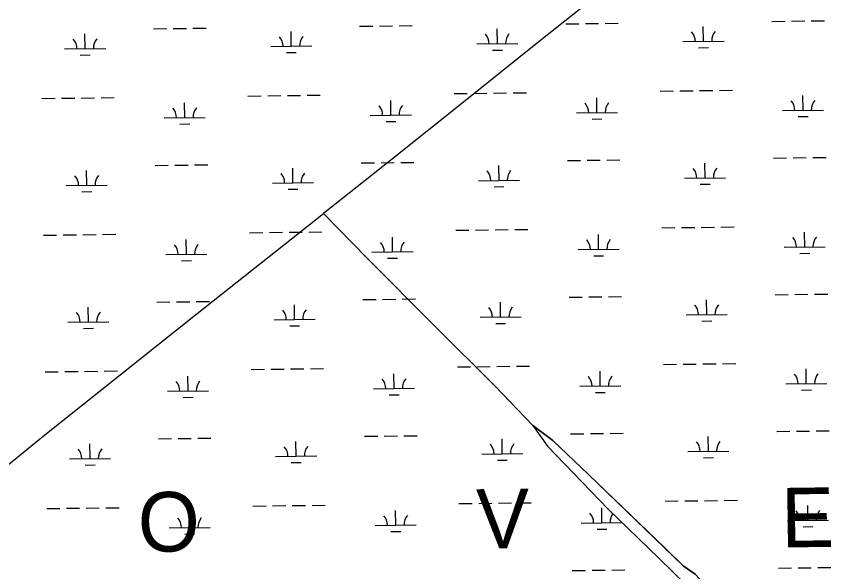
# Model space of a CAD drawing. Extents: x 3694830 to 3732949, y 415201 to 440970.
# Drawn here: x 3721259 to 3723273, y 422881 to 424231 of the extents above; entities that cross this region are included whole.
import ezdxf

# ---------------------------------------------------------------- set-up
doc = ezdxf.new("R2010")
doc.units = 0
for name, color, linetype in [('V-TOPO-GNAM-IDEN', 7, 'Continuous'), ('V-TOPO-SHOR', 7, 'Continuous'), ('V-WETL-SWMP', 7, 'Continuous')]:
    doc.layers.add(name, color=color, linetype=linetype)

msp = doc.modelspace()

# ---------------------------------------------------------------- linework, layer by layer
at = {"layer": 'V-TOPO-SHOR'}
for points in [[(3724038.3, 425348.9), (3723786.8, 425156.9), (3723547.1, 424963.7), (3723407.5, 424856.6), (3723207.5, 424699.3), (3722960.3, 424507.6), (3722773.6, 424363), (3722535.6, 424174.1), (3722351.3, 424025.9), (3722170.6, 423881.7), (3722006.1, 423752.1)], [(3721128.3, 423051.5), (3721324.1, 423210), (3721699, 423509.1), (3722006.1, 423752.1)], [(3722006.1, 423752.1), (3722111.6, 423644.1), (3722278.4, 423476.8), (3722424.2, 423332.1), (3722515.9, 423236.4), (3722551.8, 423185.8)], [(3722515.9, 423236.4), (3722564.9, 423200), (3722651.8, 423117), (3722837.2, 422938.2), (3722882.2, 422894.7), (3722911.1, 422874.5), (3722923, 422862.3), (3722926.1, 422850), (3722935.2, 422831.4), (3722965.6, 422798.2), (3723006.3, 422758.3), (3723028.1, 422743.6), (3723045.1, 422728.6), (3723084.6, 422693), (3723130.8, 422664.9), (3723153, 422652.3), (3723164, 422655), (3723176.5, 422664.2), (3723180.6, 422667.3), (3723193.3, 422674.8), (3723211.5, 422683.1), (3723238, 422684.7), (3723233.6, 422648)], [(3722551.8, 423185.8), (3722699.6, 423032.7), (3722822.2, 422913.7), (3722892.9, 422845.3)]]:
    msp.add_lwpolyline(points, dxfattribs=at)
at = {"layer": 'V-WETL-SWMP'}
for p, q in [((3722142.4, 424208.3), (3722174.4, 424208.7)), ((3722190.4, 424208.9), (3722222.4, 424209.3)), ((3722596.3, 424213.7), (3722628.3, 424214.1)), ((3722644.3, 424214.3), (3722676.3, 424214.7)), ((3722692.3, 424214.9), (3722724.3, 424215.2)), ((3723098.2, 424219.7), (3723130.2, 424220.1)), ((3723146.2, 424220.3), (3723178.2, 424220.7)), ((3723194.2, 424220.8), (3723226.2, 424221.2)), ((3721426.1, 424153.3), (3721425.6, 424189.3)), ((3721592.5, 424201.7), (3721624.5, 424202.1)), ((3721640.5, 424202.3), (3721672.5, 424202.7)), ((3721688.5, 424202.9), (3721720.5, 424203.3)), ((3721927.9, 424159.3), (3721927.5, 424195.3)), ((3722094.4, 424207.7), (3722126.4, 424208.1)), ((3722429.8, 424165.3), (3722429.4, 424201.3)), ((3722931.7, 424171.3), (3722931.2, 424207.3)), ((3722881.7, 424170.7), (3722981.7, 424171.9)), ((3721376.1, 424152.7), (3721476, 424153.9)), ((3721877.9, 424158.7), (3721977.9, 424159.9)), ((3722379.8, 424164.7), (3722479.8, 424165.9)), ((3722418, 424149.7), (3722442, 424150)), ((3722919.9, 424155.7), (3722943.9, 424156)), ((3721414.2, 424137.8), (3721438.2, 424138)), ((3721916.1, 424143.7), (3721940.1, 424144)), ((3722826.3, 424049.9), (3722858.3, 424050.3)), ((3722874.3, 424050.5), (3722906.3, 424050.9)), ((3722922.3, 424051.1), (3722954.3, 424051.5)), ((3722970.3, 424051.7), (3723002.3, 424052)), ((3721320.6, 424032), (3721352.6, 424032.4)), ((3721368.6, 424032.6), (3721400.6, 424032.9)), ((3721416.6, 424033.1), (3721448.6, 424033.5)), ((3721464.6, 424033.7), (3721496.6, 424034.1)), ((3721822.5, 424038), (3721854.5, 424038.4)), ((3721870.5, 424038.5), (3721902.5, 424038.9)), ((3721918.5, 424039.1), (3721950.5, 424039.5)), ((3721966.5, 424039.7), (3721998.5, 424040.1)), ((3722170.4, 423991.4), (3722170, 424027.4)), ((3722324.4, 424044), (3722356.4, 424044.3)), ((3722372.4, 424044.5), (3722404.4, 424044.9)), ((3722420.4, 424045.1), (3722452.4, 424045.5)), ((3722468.4, 424045.7), (3722500.4, 424046.1)), ((3722672.3, 423997.4), (3722671.9, 424033.4)), ((3723174.2, 424003.3), (3723173.7, 424039.3)), ((3721668.5, 423985.4), (3721668.1, 424021.4)), ((3722120.4, 423990.8), (3722220.4, 423992)), ((3722622.3, 423996.8), (3722722.3, 423998)), ((3723124.2, 424002.8), (3723224.2, 424003.9)), ((3723162.3, 423987.8), (3723186.3, 423988.1)), ((3721618.5, 423984.8), (3721718.5, 423986)), ((3721656.7, 423969.8), (3721680.7, 423970.1)), ((3722158.6, 423975.8), (3722182.6, 423976.1)), ((3722660.5, 423981.8), (3722684.5, 423982.1)), ((3723102.1, 423887), (3723134.1, 423887.4)), ((3723150.1, 423887.6), (3723182.1, 423888)), ((3723198.1, 423888.2), (3723230.1, 423888.6)), ((3721596.5, 423869.1), (3721628.5, 423869.5)), ((3721644.5, 423869.7), (3721676.5, 423870)), ((3721692.5, 423870.2), (3721724.5, 423870.6)), ((3722098.4, 423875.1), (3722130.4, 423875.5)), ((3722146.4, 423875.6), (3722178.4, 423876)), ((3722194.4, 423876.2), (3722226.4, 423876.6)), ((3722433.8, 423832.6), (3722433.3, 423868.6)), ((3722600.3, 423881.1), (3722632.3, 423881.4)), ((3722648.3, 423881.6), (3722680.3, 423882)), ((3722696.3, 423882.2), (3722728.3, 423882.6)), ((3722935.6, 423838.6), (3722935.2, 423874.6)), ((3721430, 423820.7), (3721429.6, 423856.7)), ((3721931.9, 423826.7), (3721931.5, 423862.7)), ((3721881.9, 423826.1), (3721981.9, 423827.3)), ((3722383.8, 423832), (3722483.8, 423833.2)), ((3722885.6, 423838), (3722985.6, 423839.2)), ((3721380, 423820.1), (3721480, 423821.3)), ((3721920.1, 423811.1), (3721944.1, 423811.4)), ((3722421.9, 423817.1), (3722445.9, 423817.4)), ((3722923.8, 423823.1), (3722947.8, 423823.3)), ((3721418.2, 423805.1), (3721442.2, 423805.4)), ((3721826.5, 423705.3), (3721858.5, 423705.7)), ((3721874.5, 423705.9), (3721906.5, 423706.3)), ((3721922.5, 423706.5), (3721954.5, 423706.8)), ((3721970.5, 423707), (3722002.5, 423707.4)), ((3722328.4, 423711.3), (3722360.4, 423711.7)), ((3722376.4, 423711.9), (3722408.4, 423712.3)), ((3722424.4, 423712.5), (3722456.3, 423712.8)), ((3722472.3, 423713), (3722504.3, 423713.4)), ((3722830.2, 423717.3), (3722862.2, 423717.7)), ((3722878.2, 423717.9), (3722910.2, 423718.2)), ((3722926.2, 423718.4), (3722958.2, 423718.8)), ((3722974.2, 423719), (3723006.2, 423719.4)), ((3723178.1, 423670.7), (3723177.7, 423706.7)), ((3721324.6, 423699.3), (3721356.6, 423699.7)), ((3721372.6, 423699.9), (3721404.6, 423700.3)), ((3721420.6, 423700.5), (3721452.6, 423700.9)), ((3721468.6, 423701.1), (3721500.6, 423701.4)), ((3721672.5, 423652.7), (3721672.1, 423688.7)), ((3722174.4, 423658.7), (3722174, 423694.7)), ((3722676.3, 423664.7), (3722675.8, 423700.7)), ((3722626.3, 423664.1), (3722726.3, 423665.3)), ((3723128.1, 423670.1), (3723228.1, 423671.3)), ((3721622.5, 423652.1), (3721722.5, 423653.3)), ((3722124.4, 423658.1), (3722224.4, 423659.3)), ((3722664.4, 423649.1), (3722688.4, 423649.4)), ((3723166.3, 423655.1), (3723190.3, 423655.4)), ((3721660.7, 423637.2), (3721684.7, 423637.5)), ((3722162.6, 423643.2), (3722186.6, 423643.4)), ((3722198.3, 423543.6), (3722230.3, 423544)), ((3722604.2, 423548.4), (3722636.2, 423548.8)), ((3722652.2, 423549), (3722684.2, 423549.4)), ((3722700.2, 423549.6), (3722732.2, 423549.9)), ((3723106.1, 423554.4), (3723138.1, 423554.8)), ((3723154.1, 423555), (3723186.1, 423555.4)), ((3723202.1, 423555.5), (3723234.1, 423555.9)), ((3721434, 423488), (3721433.6, 423524)), ((3721600.5, 423536.4), (3721632.5, 423536.8)), ((3721648.5, 423537), (3721680.5, 423537.4)), ((3721696.5, 423537.6), (3721728.5, 423538)), ((3721935.9, 423494), (3721935.4, 423530)), ((3722102.4, 423542.4), (3722134.4, 423542.8)), ((3722150.4, 423543), (3722182.4, 423543.4)), ((3722437.7, 423500), (3722437.3, 423536)), ((3722939.6, 423506), (3722939.2, 423542)), ((3722889.6, 423505.4), (3722989.6, 423506.6)), ((3721384, 423487.4), (3721484, 423488.6)), ((3721885.9, 423493.4), (3721985.9, 423494.6)), ((3722387.7, 423499.4), (3722487.7, 423500.6)), ((3722425.9, 423484.4), (3722449.9, 423484.7)), ((3722927.8, 423490.4), (3722951.8, 423490.7)), ((3721422.2, 423472.4), (3721446.2, 423472.7)), ((3721924, 423478.4), (3721948, 423478.7)), ((3722834.2, 423384.6), (3722866.2, 423385)), ((3722882.2, 423385.2), (3722914.2, 423385.6)), ((3722930.2, 423385.8), (3722962.2, 423386.2)), ((3722978.2, 423386.4), (3723010.2, 423386.7)), ((3721328.6, 423366.7), (3721360.6, 423367.1)), ((3721376.6, 423367.3), (3721408.6, 423367.6)), ((3721424.6, 423367.8), (3721456.6, 423368.2)), ((3721472.6, 423368.4), (3721504.6, 423368.8)), ((3721830.5, 423372.7), (3721862.5, 423373.1)), ((3721878.5, 423373.2), (3721910.4, 423373.6)), ((3721926.4, 423373.8), (3721958.4, 423374.2)), ((3721974.4, 423374.4), (3722006.4, 423374.8)), ((3722332.3, 423378.7), (3722364.3, 423379)), ((3722380.3, 423379.2), (3722412.3, 423379.6)), ((3722428.3, 423379.8), (3722460.3, 423380.2)), ((3722476.3, 423380.4), (3722508.3, 423380.8)), ((3722680.2, 423332.1), (3722679.8, 423368.1)), ((3723182.1, 423338), (3723181.7, 423374)), ((3721676.5, 423320.1), (3721676, 423356.1)), ((3722178.3, 423326.1), (3722177.9, 423362.1)), ((3722128.4, 423325.5), (3722228.3, 423326.7)), ((3722630.2, 423331.5), (3722730.2, 423332.7)), ((3723132.1, 423337.4), (3723232.1, 423338.6)), ((3723170.3, 423322.5), (3723194.3, 423322.8)), ((3721626.5, 423319.5), (3721726.5, 423320.7)), ((3721664.7, 423304.5), (3721688.7, 423304.8)), ((3722166.5, 423310.5), (3722190.5, 423310.8)), ((3722668.4, 423316.5), (3722692.4, 423316.8)), ((3722564.9, 423200), (3722515.9, 423236.4)), ((3722515.9, 423236.4), (3722551.8, 423185.8)), ((3723110.1, 423221.7), (3723142.1, 423222.1)), ((3723158.1, 423222.3), (3723190.1, 423222.7)), ((3723206.1, 423222.9), (3723238.1, 423223.3)), ((3721604.5, 423203.8), (3721636.4, 423204.2)), ((3721652.4, 423204.4), (3721684.4, 423204.7)), ((3721700.4, 423204.9), (3721732.4, 423205.3)), ((3722106.3, 423209.8), (3722138.3, 423210.2)), ((3722154.3, 423210.3), (3722186.3, 423210.7)), ((3722202.3, 423210.9), (3722234.3, 423211.3)), ((3722441.7, 423167.3), (3722441.3, 423203.3)), ((3722608.2, 423215.8), (3722640.2, 423216.1)), ((3722656.2, 423216.3), (3722688.2, 423216.7)), ((3722704.2, 423216.9), (3722736.2, 423217.3)), ((3722943.6, 423173.3), (3722943.1, 423209.3)), ((3721438, 423155.4), (3721437.5, 423191.4)), ((3721939.8, 423161.4), (3721939.4, 423197.4)), ((3722551.8, 423185.8), (3722699.6, 423032.7)), ((3722651.8, 423117), (3722564.9, 423200)), ((3721889.8, 423160.8), (3721989.8, 423162)), ((3722391.7, 423166.7), (3722491.7, 423167.9)), ((3722893.6, 423172.7), (3722993.6, 423173.9)), ((3721388, 423154.8), (3721487.9, 423156)), ((3721928, 423145.8), (3721952, 423146.1)), ((3722429.9, 423151.8), (3722453.9, 423152.1)), ((3722931.8, 423157.8), (3722955.8, 423158)), ((3721426.1, 423139.8), (3721450.1, 423140.1)), ((3722882.2, 422894.7), (3722651.8, 423117)), ((3721882.4, 423040.6), (3721914.4, 423041)), ((3721930.4, 423041.2), (3721962.4, 423041.5)), ((3721978.4, 423041.7), (3722010.4, 423042.1)), ((3722336.3, 423046), (3722368.3, 423046.4)), ((3722384.3, 423046.6), (3722416.3, 423047)), ((3722432.3, 423047.1), (3722464.3, 423047.5)), ((3722480.3, 423047.7), (3722512.3, 423048.1)), ((3722838.2, 423052), (3722870.2, 423052.4)), ((3722886.2, 423052.6), (3722918.2, 423052.9)), ((3722934.2, 423053.1), (3722966.2, 423053.5)), ((3722982.2, 423053.7), (3723014.2, 423054.1)), ((3723186.1, 423005.4), (3723185.6, 423041.4)), ((3721332.5, 423034), (3721364.5, 423034.4)), ((3721380.5, 423034.6), (3721412.5, 423035)), ((3721428.5, 423035.2), (3721460.5, 423035.6)), ((3721476.5, 423035.7), (3721508.5, 423036.1)), ((3721680.4, 422987.4), (3721680, 423023.4)), ((3721834.4, 423040), (3721866.4, 423040.4)), ((3722182.3, 422993.4), (3722181.9, 423029.4)), ((3722684.2, 422999.4), (3722683.8, 423035.4)), ((3722699.6, 423032.7), (3722822.2, 422913.7)), ((3723136.1, 423004.8), (3723236.1, 423006)), ((3721630.4, 422986.8), (3721730.4, 422988)), ((3722132.3, 422992.8), (3722232.3, 422994)), ((3722634.2, 422998.8), (3722733.3, 423000)), ((3722672.4, 422983.8), (3722696.4, 422984.1)), ((3723174.2, 422989.8), (3723198.2, 422990.1)), ((3721668.6, 422971.9), (3721692.6, 422972.1)), ((3722170.5, 422977.8), (3722194.5, 422978.1)), ((3722822.2, 422913.7), (3722892.9, 422845.3)), ((3722612.2, 422883.1), (3722644.2, 422883.5)), ((3722660.2, 422883.7), (3722692.2, 422884.1)), ((3722708.2, 422884.3), (3722740.2, 422884.6)), ((3722911.1, 422874.5), (3722882.2, 422894.7)), ((3723114, 422889.1), (3723146, 422889.5)), ((3723162, 422889.7), (3723194, 422890)), ((3723210, 422890.2), (3723242, 422890.6))]:
    msp.add_line(p, q, dxfattribs=at)
for centre, start, end in [((3722374.6, 424165.1), 359.9115, 41.4552), ((3722485, 424166.4), 139.9115, 181.4552), ((3722876.4, 424171.1), 359.9115, 41.4552), ((3722986.9, 424172.4), 139.9115, 181.4552), ((3721370.8, 424153.1), 359.9115, 41.4552), ((3721481.3, 424154.5), 139.9115, 181.4552), ((3721872.7, 424159.1), 359.9115, 41.4552), ((3721983.2, 424160.4), 139.9115, 181.4552), ((3721613.3, 423985.2), 359.9115, 41.4552), ((3721723.8, 423986.5), 139.9115, 181.4552), ((3722115.2, 423991.2), 359.9115, 41.4552), ((3722225.6, 423992.5), 139.9115, 181.4552), ((3722617, 423997.2), 359.9115, 41.4552), ((3722727.5, 423998.5), 139.9115, 181.4552), ((3723118.9, 424003.2), 359.9115, 41.4552), ((3723229.4, 424004.5), 139.9115, 181.4552), ((3721876.6, 423826.5), 359.9115, 41.4552), ((3721987.1, 423827.8), 139.9115, 181.4552), ((3722378.5, 423832.5), 359.9115, 41.4552), ((3722489, 423833.8), 139.9115, 181.4552), ((3722880.4, 423838.4), 359.9115, 41.4552), ((3722990.9, 423839.8), 139.9115, 181.4552), ((3721374.8, 423820.5), 359.9115, 41.4552), ((3721485.3, 423821.8), 139.9115, 181.4552), ((3722621, 423664.5), 359.9115, 41.4552), ((3722731.5, 423665.8), 139.9115, 181.4552), ((3723122.9, 423670.5), 359.9115, 41.4552), ((3723233.4, 423671.8), 139.9115, 181.4552), ((3721617.3, 423652.6), 359.9115, 41.4552), ((3721727.7, 423653.9), 139.9115, 181.4552), ((3722119.1, 423658.5), 359.9115, 41.4552), ((3722229.6, 423659.9), 139.9115, 181.4552), ((3722493, 423501.1), 139.9115, 181.4552), ((3722884.4, 423505.8), 359.9115, 41.4552), ((3722994.8, 423507.1), 139.9115, 181.4552), ((3721378.7, 423487.8), 359.9115, 41.4552), ((3721489.2, 423489.2), 139.9115, 181.4552), ((3721880.6, 423493.8), 359.9115, 41.4552), ((3721991.1, 423495.1), 139.9115, 181.4552), ((3722382.5, 423499.8), 359.9115, 41.4552), ((3721621.2, 423319.9), 359.9115, 41.4552), ((3721731.7, 423321.2), 139.9115, 181.4552), ((3722123.1, 423325.9), 359.9115, 41.4552), ((3722233.6, 423327.2), 139.9115, 181.4552), ((3722625, 423331.9), 359.9115, 41.4552), ((3722735.5, 423333.2), 139.9115, 181.4552), ((3723126.8, 423337.9), 359.9115, 41.4552), ((3723237.3, 423339.2), 139.9115, 181.4552), ((3721884.6, 423161.2), 359.9115, 41.4552), ((3721995.1, 423162.5), 139.9115, 181.4552), ((3722386.5, 423167.2), 359.9115, 41.4552), ((3722496.9, 423168.5), 139.9115, 181.4552), ((3722888.3, 423173.1), 359.9115, 41.4552), ((3722998.8, 423174.5), 139.9115, 181.4552), ((3721382.7, 423155.2), 359.9115, 41.4552), ((3721493.2, 423156.5), 139.9115, 181.4552), ((3722628.9, 422999.2), 359.9115, 41.4552), ((3722739.4, 423000.5), 143.3704, 181.4552), ((3723130.8, 423005.2), 359.9115, 41.4552), ((3723241.3, 423006.5), 139.9115, 181.4552), ((3721625.2, 422987.3), 359.9115, 41.4552), ((3721735.7, 422988.6), 139.9115, 181.4552), ((3722127.1, 422993.2), 359.9115, 41.4552), ((3722237.6, 422994.6), 139.9115, 181.4552)]:
    msp.add_arc(centre, 35.2, start, end, dxfattribs=at)

# ---------------------------------------------------------------- texts
at = {"layer": 'V-TOPO-GNAM-IDEN'}
for s, p in [('V', (3722379.2, 422936)), ('E', (3723121.6, 422939.1)), ('O', (3721555.2, 422928.3))]:
    msp.add_text(s, height=145, rotation=0.7812, dxfattribs=at).set_placement(p)

doc.saveas('drawing.dxf')
